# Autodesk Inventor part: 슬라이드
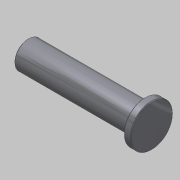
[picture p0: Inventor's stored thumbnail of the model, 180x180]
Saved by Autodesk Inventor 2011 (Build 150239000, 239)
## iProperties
Created: 2013-06
Part Number: 슬라이드
Document SubType Name: Modeling
Designer: SeoGD™[esajin.kr]
Density: 1 g/cm^3
Author: SeoGD™[esajin.kr]
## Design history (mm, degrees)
sketch "스케치1"
  geometry: L1 (-75, 162)-(-75, 58) reference; L2 (-148, 110)-(22, 110); L3 (-148, 110)-(-148, 129); L4 (-148, 129)-(12, 129); L5 (12, 129)-(12, 139); L6 (12, 139)-(22, 139); L7 (22, 139)-(22, 110); 2 further points
  constraints: 12 end point, 3 parallel, 3 perpendicular, 1 midpoint, 1 point on line
  dimensions: "d0" = 58 diameter of L6 L2; "d1" = 38 diameter of L4 L2; "d2" = 10 distance of L5.end L6.end; "d3" = 170 distance of L2.start L2.end; "d4" = 73 distance between parallel lines of L3 L1
revolve "회전1" sketch "스케치1" stored, may be unused: angle "d5" = 90 deg
hole "구멍1" diameter "d11" = 13.376; stored, may be unused: countersink angle "d15" = 90 deg, drill point angle "d17" = 118 deg; dims "d9" = 10, "d10" = 10, "d12" = 22, "d13" = 4, "d14" = 2, "d16" = 25
chamfer "모따기1" distance "d6" = 1; stored, may be unused: second distance "d7" = 2, angle "d8" = 45 deg
node "솔리드1"
node "참조1"
